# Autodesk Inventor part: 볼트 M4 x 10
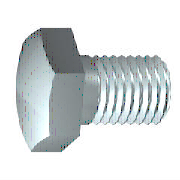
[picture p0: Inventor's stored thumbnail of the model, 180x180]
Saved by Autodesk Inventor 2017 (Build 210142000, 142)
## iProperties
Created: 2012-02
Part Number: 볼트 M4 x 10
Material: 스테인리스강
Description: 6각 머리 나사
Document SubType Name: Modeling
Standard: ISO 4017
Designer: mduedu
Standard Revision: Third edition 1999-08-15
Standards Organization: ISO
Language: ko-KR
Size Designation: M4 x 10
Categories: <MemberInstance><Categories><Category DisplayName="조임쇠" InternalName="e4da775c-781d-43d5-af7c-5136215cf5a6" Mnemonic="FSTN"><Category DisplayName="볼트" InternalN
Density: 8.08 g/cm^3
Appearance: 기본값
IsCustomPart: 0
Author: mduedu
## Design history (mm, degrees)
sketch "스케치1"
  geometry: L1 (0, 3.015)-(0, 2); L2 (1.25, 2)-(10, 2); L3 (10, 2)-(10, 0); L4 (10, 0)-(-0.4, 0); L5 (-2.48, 0)-(12.08, 0) reference; L6 (-0.4, 0)-(-0.4, 3.015); L7 (-0.4, 3.015)-(0, 3.015); L8 (1.25, 2)-(0.82, 2); L9 (0.82, 2)-(0, 2); L10 (0, -0.603)-(0, 3.618) reference
  constraints: 16 end point, 2 collinear, 2 perpendicular, 1 parallel
  dimensions: "d0" = 10 distance between parallel lines of L3 L1 (= NLG); "d1" = 8.75 distance from line of L2.start L3 (= GEL); "d2" = 4 diameter of L2 L4 (= GD); "d9" = 0.4001 distance between parallel lines of L6 L1 (computed from SD); "d10" = 6.03 diameter of L7 L4 (= SD2); "d13" = 0.42952 distance of L2.start L8.end (computed from GAL); "d14" = 4 diameter of L9 L4 (= BDM)
revolve "본체" sketch "스케치1" stored, may be unused: angle "d12" = 90 deg
sketch "스케치2"
  geometry: L1 (0, 4.041)-(3.5, 2.021); L2 (3.5, 2.021)-(3.5, -2.021); L3 (3.5, -2.021)-(0, -4.041); L4 (0, -4.041)-(-3.5, -2.021); L5 (-3.5, -2.021)-(-3.5, 2.021); L6 (-3.5, 2.021)-(0, 4.041); 2 further points
  constraints: 12 end point, 1 coincident, 1 vertical, 11 other
  dimensions: "d11" = 7 distance between parallel lines of L5 L2 (= SW)
extrude "머리" join sketch "스케치2" distance "d3" = 2.4 (= KOH - SD); taper "d4" = 0 deg
sketch "스케치4"
  geometry: L1 (-2.8, 3.5)-(-2.8, 4.041); L2 (-2.8, 4.041)-(-2.487, 4.041); L3 (-2.487, 4.041)-(-2.8, 3.5); L4 (-3.28, 0)-(0.08, 0) reference; L5 (-0.4, 4.041)-(-2.8, 4.041) reference; L6 (-2.8, 2.021)-(-2.8, 4.041) reference
  constraints: 6 end point, 2 collinear, 1 perpendicular, 1 vertical
  dimensions: "d5" = 30 deg angle of L3 L1 (= ANG1); "d19" = 7 diameter of L1.start L4 (= SW0)
revolve "모따기1" sketch "스케치4" stored, may be unused: angle "d21" = 90 deg
workplane "Work Plane1"
body "Solid1"
feature "스레드" dims "d15" = 8.75 (= GEL), "d16" = 0
chamfer "모따기2" distance "d6" = 0.42941 (= -0.5 x SPD + 0.5 x GD); stored, may be unused: second distance "d7" = 0.42952 (computed from GUL), angle "d55" = 45 deg
other parameters: "NLG" = 10 [user parameter; used in 1 equation term], "GD" = 4 (= NND) [user parameter; used in 2 equation terms], "BDM" = 4 (= NND) [user parameter; used in 1 equation term], "KOH" = 2.8 [user parameter; used in 1 equation term], "GEL" = 8.75 [user parameter; used in 2 equation terms], "SW" = 7 [user parameter; used in 2 equation terms], "SW0" = 7 (= SW) [user parameter; used in 1 equation term], "SPD" = 3.14117 (= NND - 1.2269 x PTC) [user parameter; used in 1 equation term], "SD2" = 6.03 [user parameter; used in 2 equation terms], "SD" = 0.4 [user parameter; used in 2 equation terms], "ANG1" = 30 deg [user parameter; used in 1 equation term], "GAL" = 0.42941 (= 0.61345 x PTC) [user parameter; used in 1 equation term], "GUL" = 0.42941 (= 0.61345 x PTC) [user parameter; used in 1 equation term], "d8" = 0, "RR" = 0.2 [user parameter], "d57" = 0, "d58" = 0, "TPU" = 14.28571 (computed from PTC) [user parameter], "GD1" = 3.14117 (= THREADDIA - 1.2269 x PTC) [user parameter], "THREADDIA" = 4 [user parameter; used in 1 equation term], "SDH" = 6.03 (= SD2) [user parameter], "SDHG" = 2.1 [user parameter], "TOA" = 30 deg [user parameter], "PTC" = 0.7 [user parameter; used in 5 equation terms], "NND" = 4 [user parameter; used in 3 equation terms], "E0" = 8.085 [user parameter]
